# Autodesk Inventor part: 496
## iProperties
Author: Administrator
Shininess: 64.0
Angle Display Precision: 2
Document Length Units: 11272
Document Angle Units: 11286
Document Time Units: 11279
Document Mass Units: 11290
Document Length Units Precision: 3
Document Angle Units Precision: 2
Compacted: True
PropertySet Name: _Private Model Information
Created: 2002-03
Part Number: 496
Material: Stainless Steel, 440C
Document SubType Name: Modeling
Designer: Administrator
Control State: 0
Master: False
Checked Out: False
PropertySet Name: Design Tracking Control
Density: 0.0
Volumn: 0.0
Area: 0.0
PropertySet Name: Model Information
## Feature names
1. Revolution1
